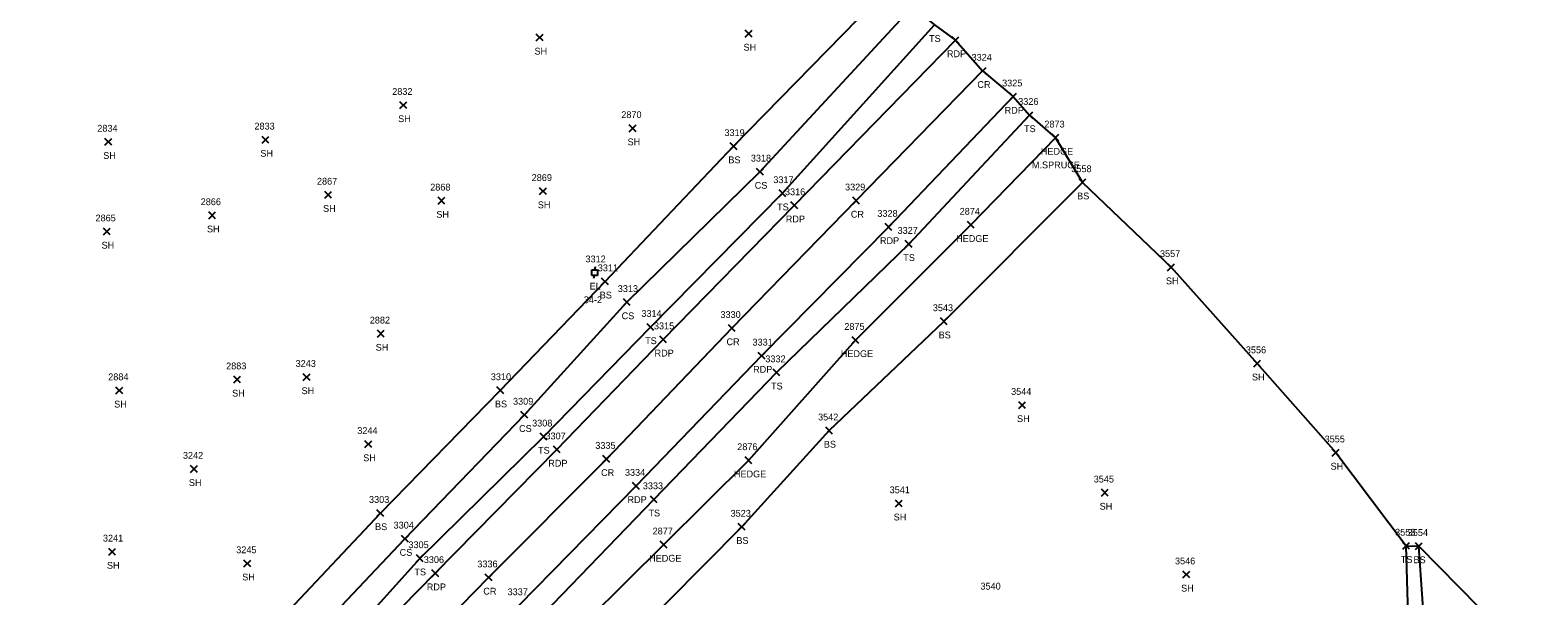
# Model space of a CAD drawing. Extents: x 1472233 to 1475777, y 540726 to 543442.
# Drawn here: x 1474263.9 to 1474707, y 542388.4 to 542554.7 of the extents above; entities that cross this region are included whole.
import ezdxf

# ---------------------------------------------------------------- set-up
doc = ezdxf.new("R2010")
doc.units = 0
for name, color, linetype in [('L_A', 7, 'Continuous'), ('L_C', 7, 'Continuous'), ('L_I', 7, 'Continuous'), ('L_TIC', 7, 'Continuous'), ('LAHR', 7, 'Continuous'), ('LELB', 7, 'Continuous'), ('LSOGP', 7, 'Continuous'), ('P_A', 7, 'Continuous'), ('P_I', 7, 'Continuous'), ('P_TIC', 7, 'Continuous'), ('PET', 7, 'Continuous'), ('PRC', 7, 'Continuous'), ('U_A', 7, 'Continuous'), ('U_C', 7, 'Continuous'), ('U_I', 7, 'Continuous'), ('UEPT', 7, 'Continuous')]:
    doc.layers.add(name, color=color, linetype=linetype)

msp = doc.modelspace()

# ---------------------------------------------------------------- linework, layer by layer
at = {"layer": 'L_TIC'}
for points in [[(1474474.07, 542552.66), (1474476.07, 542554.66)], [(1474476.07, 542552.66), (1474474.07, 542554.66)], [(1474412.65, 542551.51), (1474414.65, 542553.51)], [(1474414.65, 542551.51), (1474412.65, 542553.51)], [(1474372.59, 542531.65), (1474374.59, 542533.65)], [(1474374.59, 542531.65), (1474372.59, 542533.65)], [(1474556.58, 542528.71), (1474558.58, 542530.71)], [(1474558.58, 542528.71), (1474556.58, 542530.71)], [(1474439.99, 542524.84), (1474441.99, 542526.84)], [(1474441.99, 542524.84), (1474439.99, 542526.84)], [(1474564.22, 542522.07), (1474566.22, 542524.07)], [(1474566.22, 542522.07), (1474564.22, 542524.07)], [(1474285.94, 542520.84), (1474287.94, 542522.84)], [(1474287.94, 542520.84), (1474285.94, 542522.84)], [(1474332.11, 542521.47), (1474334.11, 542523.47)], [(1474334.11, 542521.47), (1474332.11, 542523.47)], [(1474469.66, 542519.55), (1474471.66, 542521.55)], [(1474471.66, 542519.55), (1474469.66, 542521.55)], [(1474477.4, 542512.06), (1474479.4, 542514.06)], [(1474479.4, 542512.06), (1474477.4, 542514.06)], [(1474572.15, 542508.94), (1474574.15, 542510.94)], [(1474574.15, 542508.94), (1474572.15, 542510.94)], [(1474350.52, 542505.27), (1474352.52, 542507.27)], [(1474352.52, 542505.27), (1474350.52, 542507.27)], [(1474413.64, 542506.34), (1474415.64, 542508.34)], [(1474415.64, 542506.34), (1474413.64, 542508.34)], [(1474484.02, 542505.72), (1474486.02, 542507.72)], [(1474486.02, 542505.72), (1474484.02, 542507.72)], [(1474383.81, 542503.54), (1474385.81, 542505.54)], [(1474385.81, 542503.54), (1474383.81, 542505.54)], [(1474316.42, 542499.24), (1474318.42, 542501.24)], [(1474318.42, 542499.24), (1474316.42, 542501.24)], [(1474539.33, 542496.43), (1474541.33, 542498.43)], [(1474541.33, 542496.43), (1474539.33, 542498.43)], [(1474285.46, 542494.47), (1474287.46, 542496.47)], [(1474287.46, 542494.47), (1474285.46, 542496.47)], [(1474521.09, 542490.81), (1474523.09, 542492.81)], [(1474523.09, 542490.81), (1474521.09, 542492.81)], [(1474598.19, 542483.98), (1474600.19, 542485.98)], [(1474600.19, 542483.98), (1474598.19, 542485.98)], [(1474431.87, 542479.81), (1474433.87, 542481.81)], [(1474433.87, 542479.81), (1474431.87, 542481.81)], [(1474438.3, 542473.71), (1474440.3, 542475.71)], [(1474440.3, 542473.71), (1474438.3, 542475.71)], [(1474366, 542464.45), (1474368, 542466.45)], [(1474368, 542464.45), (1474366, 542466.45)], [(1474445.25, 542466.39), (1474447.25, 542468.39)], [(1474447.25, 542466.39), (1474445.25, 542468.39)], [(1474531.44, 542468.08), (1474533.44, 542470.08)], [(1474533.44, 542468.08), (1474531.44, 542470.08)], [(1474505.44, 542462.58), (1474507.44, 542464.58)], [(1474507.44, 542462.58), (1474505.44, 542464.58)], [(1474623.47, 542455.71), (1474625.47, 542457.71)], [(1474625.47, 542455.71), (1474623.47, 542457.71)], [(1474323.79, 542450.98), (1474325.79, 542452.98)], [(1474325.79, 542450.98), (1474323.79, 542452.98)], [(1474344.21, 542451.69), (1474346.21, 542453.69)], [(1474346.21, 542451.69), (1474344.21, 542453.69)], [(1474482.23, 542453.06), (1474484.23, 542455.06)], [(1474484.23, 542453.06), (1474482.23, 542455.06)], [(1474289.15, 542447.76), (1474291.15, 542449.76)], [(1474291.15, 542447.76), (1474289.15, 542449.76)], [(1474401.09, 542447.8), (1474403.09, 542449.8)], [(1474403.09, 542447.8), (1474401.09, 542449.8)], [(1474554.45, 542443.47), (1474556.45, 542445.47)], [(1474556.45, 542443.47), (1474554.45, 542445.47)], [(1474408.17, 542440.59), (1474410.17, 542442.59)], [(1474410.17, 542440.59), (1474408.17, 542442.59)], [(1474413.78, 542434.18), (1474415.78, 542436.18)], [(1474415.78, 542434.18), (1474413.78, 542436.18)], [(1474497.72, 542435.96), (1474499.72, 542437.96)], [(1474499.72, 542435.96), (1474497.72, 542437.96)], [(1474362.33, 542431.97), (1474364.33, 542433.97)], [(1474364.33, 542431.97), (1474362.33, 542433.97)], [(1474646.57, 542429.49), (1474648.57, 542431.49)], [(1474648.57, 542429.49), (1474646.57, 542431.49)], [(1474311.1, 542424.69), (1474313.1, 542426.69)], [(1474313.1, 542424.69), (1474311.1, 542426.69)], [(1474474.02, 542427.22), (1474476.02, 542429.22)], [(1474476.02, 542427.22), (1474474.02, 542429.22)], [(1474446.23, 542415.74), (1474448.23, 542417.74)], [(1474448.23, 542415.74), (1474446.23, 542417.74)], [(1474578.72, 542417.72), (1474580.72, 542419.72)], [(1474580.72, 542417.72), (1474578.72, 542419.72)], [(1474365.86, 542411.72), (1474367.86, 542413.72)], [(1474367.86, 542411.72), (1474365.86, 542413.72)], [(1474518.21, 542414.56), (1474520.21, 542416.56)], [(1474520.21, 542414.56), (1474518.21, 542416.56)], [(1474472.02, 542407.66), (1474474.02, 542409.66)], [(1474474.02, 542407.66), (1474472.02, 542409.66)], [(1474373.08, 542404.17), (1474375.08, 542406.17)], [(1474375.08, 542404.17), (1474373.08, 542406.17)], [(1474449.11, 542402.45), (1474451.11, 542404.45)], [(1474451.11, 542402.45), (1474449.11, 542404.45)], [(1474667.28, 542402.09), (1474669.28, 542404.09)], [(1474669.28, 542402.09), (1474667.28, 542404.09)], [(1474287.02, 542400.36), (1474289.02, 542402.36)], [(1474289.02, 542400.36), (1474287.02, 542402.36)], [(1474377.44, 542398.42), (1474379.44, 542400.42)], [(1474379.44, 542398.42), (1474377.44, 542400.42)], [(1474671, 542402), (1474673, 542404)], [(1474673, 542402), (1474671, 542404)], [(1474326.76, 542396.93), (1474328.76, 542398.93)], [(1474328.76, 542396.93), (1474326.76, 542398.93)], [(1474602.66, 542393.65), (1474604.66, 542395.65)], [(1474604.66, 542393.65), (1474602.66, 542395.65)]]:
    msp.add_lwpolyline(points, dxfattribs=at)
at = {"layer": 'LAHR'}
msp.add_lwpolyline([(1474565.22, 542523.07), (1474540.33, 542497.43), (1474506.44, 542463.58), (1474475.02, 542428.22), (1474450.11, 542403.45), (1474416.63, 542370.29), (1474393.32, 542345.12), (1474368.26, 542319.47), (1474350.54, 542302.3)], dxfattribs=at)
at = {"layer": 'LELB'}
for points in [[(1474160.18, 542201.33), (1474168.88, 542204.85), (1474199.76, 542233.59), (1474232.18, 542271.17), (1474267.12, 542308.88), (1474299.34, 542340.87), (1474332.23, 542375.84), (1474366.86, 542412.72), (1474402.09, 542448.8), (1474432.87, 542480.81), (1474470.66, 542520.55), (1474516.44, 542567.56)], [(1473906.31, 542415.11), (1473928.48, 542392.67), (1473965.32, 542353.55), (1473983.11, 542341.15), (1474025.37, 542302.76), (1474058.47, 542271.21), (1474097.38, 542229.91), (1474138.31, 542198.57), (1474151.22, 542193.05), (1474160.36, 542193.58), (1474173.74, 542199.32), (1474204.33, 542229.44), (1474238.35, 542265.7), (1474274.3, 542301.58), (1474305.47, 542334.43), (1474340.21, 542369.37), (1474374.08, 542405.17), (1474409.17, 542441.59), (1474439.3, 542474.71), (1474478.4, 542513.06), (1474523.25, 542561.51)], [(1474243.66, 542261.29), (1474279.95, 542296.56), (1474311.01, 542327.87), (1474346, 542363.32), (1474378.44, 542399.42), (1474414.78, 542435.18), (1474446.25, 542467.39), (1474485.02, 542506.72), (1474529.67, 542556.23)], [(1474557.58, 542529.71), (1474522.09, 542491.81), (1474483.23, 542454.06), (1474447.23, 542416.74), (1474412.06, 542380.25), (1474379.37, 542349.41), (1474343.6, 542316.04), (1474316.31, 542281.15), (1474280.69, 542244.87), (1474246.56, 542209.49), (1474213.41, 542173.59), (1474208.02, 542167.68), (1474200.74, 542153.13), (1474198.37, 542139.48), (1474200.45, 542125.52), (1474209.35, 542108.6), (1474232.76, 542086.13), (1474267.25, 542051.54)], [(1474216.26, 542148.6), (1474223.4, 542155.26), (1474247.23, 542182.33), (1474283.13, 542216.31), (1474314.57, 542247.53), (1474347.6, 542281.92), (1474378.54, 542314.6), (1474411.37, 542346.77), (1474440.49, 542375.76), (1474473.02, 542408.66), (1474498.72, 542436.96), (1474532.44, 542469.08), (1474573.15, 542509.94)], [(1474224.4, 542132.89), (1474214.67, 542147.07), (1474216.26, 542148.6), (1474233.55, 542141.27), (1474249.83, 542126.15), (1474276.9, 542111.5), (1474307.13, 542091.56), (1474326.64, 542097.52), (1474365.64, 542128.15), (1474400.6, 542150.98), (1474435.75, 542164.06), (1474480.57, 542181.17), (1474523.3, 542196.58), (1474566.56, 542214.53), (1474608.16, 542237.53), (1474651, 542255.91), (1474666.23, 542275.2), (1474669.38, 542296.35), (1474671.7, 542325.64), (1474674.17, 542372.03), (1474672, 542403)], [(1474223.4, 542155.26), (1474236.8, 542144.47), (1474252.42, 542130.69), (1474282.17, 542118.73), (1474310.27, 542099.34), (1474324.58, 542102.51), (1474358.13, 542136.49), (1474395.06, 542159.11), (1474432.5, 542171.12), (1474478.94, 542185.5), (1474519.44, 542203.63), (1474563.79, 542220.16), (1474604.8, 542244.06), (1474646.81, 542262.31), (1474659.39, 542277.16), (1474666.31, 542299.31), (1474664.16, 542325.35), (1474669.11, 542372.81), (1474668.28, 542403.09)]]:
    msp.add_lwpolyline(points, dxfattribs=at)
at = {"layer": 'LSOGP'}
msp.add_lwpolyline([(1474254.32, 542799.27), (1474306.41, 542750.42), (1474344.02, 542718.74), (1474392.64, 542668.39), (1474427.2, 542641.66), (1474468.26, 542603.61), (1474507.18, 542581.48), (1474516.44, 542567.56), (1474523.25, 542561.51), (1474529.67, 542556.23), (1474535.84, 542551.74), (1474543.83, 542542.7), (1474552.8, 542535.14), (1474557.58, 542529.71), (1474565.22, 542523.07), (1474573.15, 542509.94), (1474599.19, 542484.98), (1474624.47, 542456.71), (1474647.57, 542430.49), (1474668.28, 542403.09), (1474672, 542403), (1474695.38, 542379.16), (1474702.24, 542370.13), (1474727.33, 542341.59)], dxfattribs=at)
at = {"layer": 'P_TIC'}
for points in [[(1474534.84, 542550.74), (1474536.84, 542552.74)], [(1474536.84, 542550.74), (1474534.84, 542552.74)], [(1474542.83, 542541.7), (1474544.83, 542543.7)], [(1474544.83, 542541.7), (1474542.83, 542543.7)], [(1474551.8, 542534.14), (1474553.8, 542536.14)], [(1474553.8, 542534.14), (1474551.8, 542536.14)], [(1474487.49, 542502.17), (1474489.49, 542504.17)], [(1474489.49, 542502.17), (1474487.49, 542504.17)], [(1474505.66, 542503.57), (1474507.66, 542505.57)], [(1474507.66, 542503.57), (1474505.66, 542505.57)], [(1474515.15, 542495.81), (1474517.15, 542497.81)], [(1474517.15, 542495.81), (1474515.15, 542497.81)], [(1474469.12, 542466.08), (1474471.12, 542468.08)], [(1474471.12, 542466.08), (1474469.12, 542468.08)], [(1474448.93, 542462.75), (1474450.93, 542464.75)], [(1474450.93, 542462.75), (1474448.93, 542464.75)], [(1474477.89, 542457.96), (1474479.89, 542459.96)], [(1474479.89, 542457.96), (1474477.89, 542459.96)], [(1474417.7, 542430.39), (1474419.7, 542432.39)], [(1474419.7, 542430.39), (1474417.7, 542432.39)], [(1474432.27, 542427.61), (1474434.27, 542429.61)], [(1474434.27, 542427.61), (1474432.27, 542429.61)], [(1474440.98, 542419.69), (1474442.98, 542421.69)], [(1474442.98, 542419.69), (1474440.98, 542421.69)], [(1474382, 542394.03), (1474384, 542396.03)], [(1474384, 542394.03), (1474382, 542396.03)], [(1474397.67, 542392.77), (1474399.67, 542394.77)], [(1474399.67, 542392.77), (1474397.67, 542394.77)]]:
    msp.add_lwpolyline(points, dxfattribs=at)
at = {"layer": 'PET'}
for points in [[(1474123.03, 542187.8), (1474134.11, 542181.83), (1474146.56, 542179.2), (1474159.49, 542179.77), (1474171.61, 542184.62), (1474182.67, 542191.86), (1474212.52, 542221.14), (1474248.16, 542257.22), (1474283.65, 542293.08), (1474314.45, 542324.63), (1474348.85, 542360.24), (1474383, 542395.03), (1474418.7, 542431.39), (1474449.93, 542463.75), (1474488.49, 542503.17), (1474535.84, 542551.74)], [(1474552.8, 542535.14), (1474516.15, 542496.81), (1474478.89, 542458.96), (1474441.98, 542420.69), (1474407.5, 542385.58), (1474376.12, 542352.84), (1474340.99, 542317.61), (1474311.34, 542286.32), (1474275.4, 542250.45), (1474241.37, 542214.59), (1474207.89, 542180.1), (1474197.08, 542165.9), (1474191.41, 542153.11), (1474190.14, 542138.73), (1474193.46, 542124.06)]]:
    msp.add_lwpolyline(points, dxfattribs=at)
at = {"layer": 'PRC'}
msp.add_lwpolyline([(1474543.83, 542542.7), (1474506.66, 542504.57), (1474470.12, 542467.08), (1474433.27, 542428.61), (1474398.67, 542393.77), (1474366.2, 542360.59), (1474332.75, 542326.31), (1474302.29, 542294.81), (1474266.94, 542258.53), (1474231.99, 542222.73), (1474195.04, 542185.73), (1474171.95, 542162.46), (1474161.37, 542151.41)], dxfattribs=at)
at = {"layer": 'UEPT'}
for p, q in [((1474428.98, 542482.6), (1474428.98, 542484.26)), ((1474428.98, 542484.26), (1474430.64, 542484.26)), ((1474429.98, 542485.1), (1474429.81, 542484.26)), ((1474430.64, 542484.26), (1474430.64, 542482.6)), ((1474430.64, 542482.6), (1474428.98, 542482.6)), ((1474429.56, 542481.76), (1474429.81, 542482.6)), ((1474429.81, 542483.43), (1474429.81, 542483.43))]:
    msp.add_line(p, q, dxfattribs=at)

# ---------------------------------------------------------------- texts
at = {"layer": 'L_A'}
for s, p in [('SH', (1474473.56, 542548.66)), ('TS', (1474528.08, 542551.23)), ('SH', (1474412.14, 542547.51)), ('SH', (1474372.08, 542527.65)), ('TS', (1474555.99, 542524.71)), ('SH', (1474331.6, 542517.47)), ('SH', (1474439.48, 542520.84)), ('HEDGE', (1474560.92, 542518.07)), ('SH', (1474285.42, 542516.84)), ('BS', (1474469.1, 542515.55)), ('CS', (1474476.85, 542508.06)), ('BS', (1474571.59, 542504.94)), ('SH', (1474350.01, 542501.27)), ('SH', (1474383.3, 542499.54)), ('SH', (1474413.12, 542502.34)), ('TS', (1474483.43, 542501.72)), ('SH', (1474315.91, 542495.24)), ('HEDGE', (1474536.03, 542492.43)), ('SH', (1474284.94, 542490.47)), ('TS', (1474520.5, 542486.81)), ('SH', (1474597.68, 542479.98)), ('BS', (1474431.31, 542475.81)), ('CS', (1474437.75, 542469.71)), ('BS', (1474530.88, 542464.08)), ('SH', (1474365.48, 542460.45)), ('TS', (1474444.66, 542462.39)), ('HEDGE', (1474502.14, 542458.58)), ('SH', (1474622.96, 542451.71)), ('SH', (1474323.28, 542446.98)), ('SH', (1474343.7, 542447.69)), ('TS', (1474481.64, 542449.06)), ('SH', (1474288.64, 542443.76)), ('BS', (1474400.53, 542443.8)), ('SH', (1474553.93, 542439.47)), ('CS', (1474407.61, 542436.59)), ('TS', (1474413.19, 542430.18)), ('BS', (1474497.16, 542431.96)), ('SH', (1474361.82, 542427.97)), ('SH', (1474646.06, 542425.49)), ('SH', (1474310.59, 542420.69)), ('HEDGE', (1474470.73, 542423.22)), ('TS', (1474445.64, 542411.74)), ('SH', (1474578.2, 542413.72)), ('BS', (1474365.3, 542407.72)), ('SH', (1474517.69, 542410.56)), ('BS', (1474471.46, 542403.66)), ('CS', (1474372.52, 542400.17)), ('HEDGE', (1474445.82, 542398.45)), ('TS', (1474666.69, 542398.09)), ('BS', (1474670.44, 542398)), ('SH', (1474286.51, 542396.36)), ('TS', (1474376.85, 542394.42)), ('SH', (1474326.25, 542392.93)), ('SH', (1474602.14, 542389.65))]:
    msp.add_text(s, height=2, dxfattribs=at).set_placement(p)
at = {"layer": 'L_C'}
msp.add_text('M.SPRUCE', height=2, dxfattribs=at).set_placement((1474558.3, 542514.07))
at = {"layer": 'L_I'}
for s, p in [('2832', (1474370.33, 542535.65)), ('3326', (1474554.27, 542532.71)), ('2870', (1474437.65, 542528.84)), ('2873', (1474561.96, 542526.07)), ('2834', (1474283.68, 542524.84)), ('2833', (1474329.85, 542525.47)), ('3319', (1474467.95, 542523.55)), ('3318', (1474475.71, 542516.06)), ('3558', (1474569.89, 542512.94)), ('2867', (1474348.22, 542509.27)), ('2869', (1474411.32, 542510.34)), ('3317', (1474482.32, 542509.72)), ('2868', (1474381.5, 542507.54)), ('2866', (1474314.06, 542503.24)), ('2874', (1474537.07, 542500.43)), ('2865', (1474283.15, 542498.47)), ('3327', (1474518.83, 542494.81)), ('3557', (1474595.93, 542487.98)), ('3311', (1474430.74, 542483.81)), ('3313', (1474436.61, 542477.71)), ('2882', (1474363.74, 542468.45)), ('3314', (1474443.55, 542470.39)), ('3543', (1474529.18, 542472.08)), ('2875', (1474503.18, 542466.58)), ('3556', (1474621.16, 542459.71)), ('3243', (1474341.95, 542455.69)), ('3332', (1474479.97, 542457.06)), ('2884', (1474286.89, 542451.76)), ('2883', (1474321.53, 542454.98)), ('3310', (1474399.31, 542451.8)), ('3544', (1474552.19, 542447.47)), ('3309', (1474405.83, 542444.59)), ('3308', (1474411.44, 542438.18)), ('3542', (1474495.46, 542439.96)), ('3244', (1474360.07, 542435.97)), ('3555', (1474644.31, 542433.49)), ('3242', (1474308.84, 542428.69)), ('2876', (1474471.71, 542431.22)), ('3333', (1474443.97, 542419.74)), ('3545', (1474576.46, 542421.72)), ('3303', (1474363.52, 542415.72)), ('3541', (1474516.51, 542418.56)), ('3523', (1474469.76, 542411.66)), ('3304', (1474370.74, 542408.17)), ('2877', (1474446.85, 542406.45)), ('3241', (1474285.33, 542404.36)), ('3305', (1474375.1, 542402.42)), ('3553', (1474665.02, 542406.09)), ('3554', (1474668.74, 542406)), ('3245', (1474324.5, 542400.93)), ('3546', (1474600.34, 542397.65)), ('3540', (1474543.18, 542390.24))]:
    msp.add_text(s, height=2, dxfattribs=at).set_placement(p)
at = {"layer": 'P_A'}
for s, p in [('RDP', (1474533.33, 542546.74)), ('CR', (1474542.27, 542537.7)), ('RDP', (1474550.28, 542530.14)), ('CR', (1474505.09, 542499.57)), ('RDP', (1474485.98, 542498.17)), ('RDP', (1474513.64, 542491.81)), ('CR', (1474468.56, 542462.08)), ('RDP', (1474447.42, 542458.75)), ('RDP', (1474476.38, 542453.96)), ('RDP', (1474416.19, 542426.39)), ('CR', (1474431.7, 542423.61)), ('RDP', (1474439.47, 542415.69)), ('RDP', (1474380.49, 542390.03)), ('CR', (1474397.1, 542388.77))]:
    msp.add_text(s, height=2, dxfattribs=at).set_placement(p)
at = {"layer": 'P_I'}
for s, p in [('3324', (1474540.57, 542545.7)), ('3325', (1474549.54, 542538.14)), ('3316', (1474485.74, 542506.17)), ('3329', (1474503.39, 542507.57)), ('3328', (1474512.89, 542499.81)), ('3330', (1474466.78, 542470.08)), ('3315', (1474447.24, 542466.75)), ('3331', (1474476.2, 542461.96)), ('3307', (1474415.36, 542434.39)), ('3335', (1474430.01, 542431.61)), ('3334', (1474438.72, 542423.69)), ('3306', (1474379.61, 542398.03)), ('3336', (1474395.35, 542396.77)), ('3337', (1474404.24, 542388.58))]:
    msp.add_text(s, height=2, dxfattribs=at).set_placement(p)
at = {"layer": 'U_A'}
msp.add_text('EL', height=2, dxfattribs=at).set_placement((1474428.35, 542478.43))
at = {"layer": 'U_C'}
msp.add_text('34-2', height=2, dxfattribs=at).set_placement((1474426.63, 542474.43))
at = {"layer": 'U_I'}
msp.add_text('3312', height=2, dxfattribs=at).set_placement((1474427.12, 542486.43))

doc.saveas('drawing.dxf')
